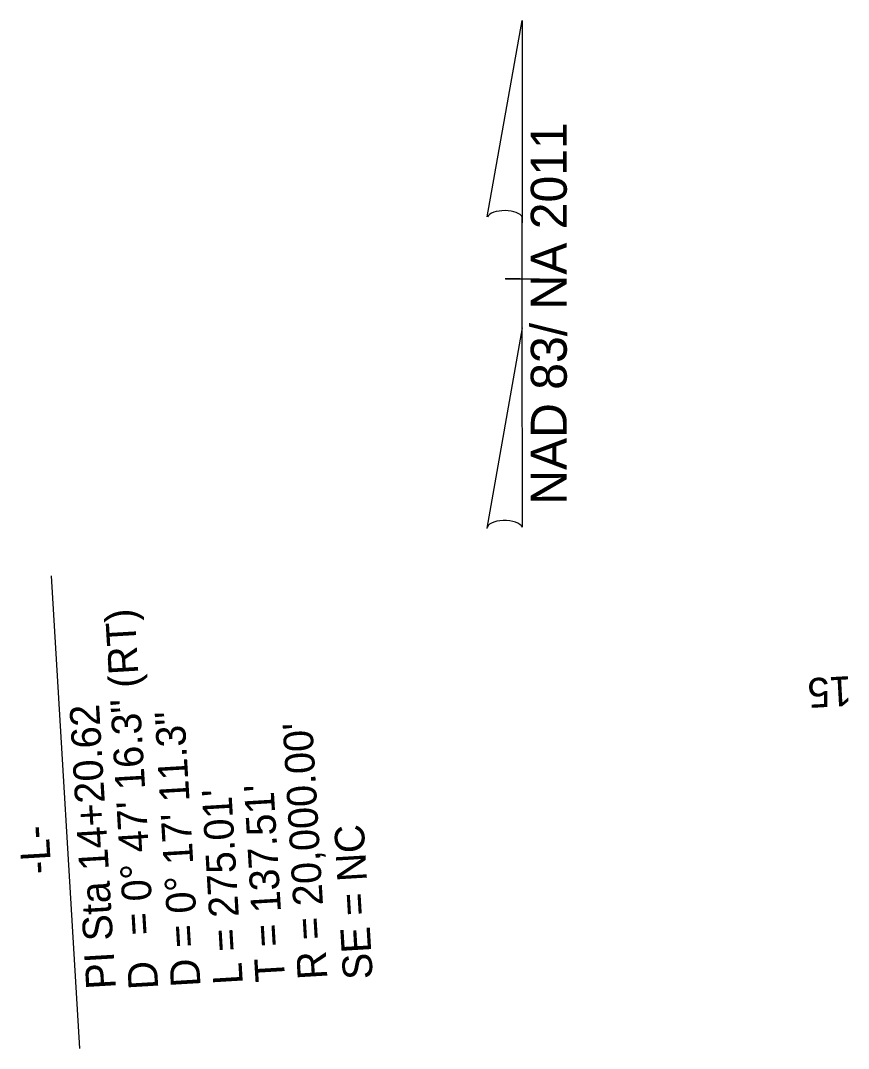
# Model space of a CAD drawing. Extents: x 2367848 to 2369479, y 800728 to 808616.
# Drawn here: x 2368442.3 to 2368637.8, y 801730 to 801972.7 of the extents above; entities that cross this region are included whole.
import ezdxf

# ---------------------------------------------------------------- set-up
doc = ezdxf.new("R2010")
doc.units = 0
for name, color, linetype in [('Prop Horizontal Alignment Curve and Spiral Data', 7, 'Continuous'), ('Prop Horizontal Alignment Tick Label', 7, 'Continuous'), ('Prop North Arrow NAD83 for Plan Sheets CELL', 7, 'Continuous')]:
    doc.layers.add(name, color=color, linetype=linetype)

msp = doc.modelspace()

# ---------------------------------------------------------------- linework, layer by layer
at = {"layer": 'Prop Horizontal Alignment Curve and Spiral Data'}
msp.add_line((2368456.3, 801729.96), (2368449.66, 801841.56), dxfattribs=at)
at = {"layer": 'Prop North Arrow NAD83 for Plan Sheets CELL'}
for p, q in [((2368552.55, 801926.37), (2368560.75, 801972.72)), ((2368560.8, 801972.72), (2368560.75, 801972.72)), ((2368560.8, 801972.72), (2368560.75, 801972.72)), ((2368560.8, 801972.72), (2368560.8, 801924.92)), ((2368560.8, 801900.12), (2368560.8, 801926.32)), ((2368560.8, 801924.92), (2368560.8, 801926.27)), ((2368556.8, 801911.72), (2368556.75, 801911.72)), ((2368560.35, 801911.72), (2368556.8, 801911.72)), ((2368556.85, 801911.72), (2368564.85, 801911.72)), ((2368560.8, 801900.12), (2368552.45, 801852.87)), ((2368560.85, 801853.07), (2368560.8, 801900.12))]:
    msp.add_line(p, q, dxfattribs=at)
for centre, start_param, end_param in [((2368556.69, 801925.88), 0.216388, 2.908219), ((2368556.69, 801852.71), 0.201328, 3.141593)]:
    msp.add_ellipse(centre, major_axis=(4.23, -0.03), ratio=0.461098, start_param=start_param, end_param=end_param, dxfattribs=at)

# ---------------------------------------------------------------- texts
at = {"layer": 'Prop Horizontal Alignment Curve and Spiral Data'}
for s, p in [('= 0%%d 47\' 16.3" (RT)', (2368473.81, 801756.86)), ('PI Sta 14+20.62', (2368464.85, 801744.13)), ('D = 0%%d 17\' 11.3"', (2368484.85, 801744.64)), ("R = 20,000.00'", (2368514.8, 801746.42)), ("T = 137.51'", (2368504.82, 801745.83)), ("L = 275.01'", (2368494.83, 801745.24)), ('-L-', (2368449.6, 801771.33)), ('SE = NC', (2368525.53, 801746.44)), ('D', (2368474.87, 801744.05))]:
    msp.add_text(s, height=7, rotation=93.403, dxfattribs=at).set_placement(p)
at = {"layer": 'Prop Horizontal Alignment Tick Label'}
msp.add_text('15', height=7, rotation=183.107, dxfattribs=at).set_placement((2368638.42, 801817.92))
at = {"layer": 'Prop North Arrow NAD83 for Plan Sheets CELL'}
msp.add_text('NAD 83/ NA 2011', height=8.5, rotation=90, dxfattribs=at).set_placement((2368571.32, 801858.37))

doc.saveas('drawing.dxf')
